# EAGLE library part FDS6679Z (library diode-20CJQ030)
Fairchild's FDS6679Z 30 Volt P-Channel PowerTrench MOSFET General Description: This P-Channel MOSFET has been designed specifically to improve the overall efficiency of DC/DC converters using either synchronous or conventional switching PWM controllers, and battery chargers. These MOSFETs feature faster switching and lower gate charge than other MOSFETs with comparable RDS(ON) specifications. The result is a MOSFET that is easy and safer to drive (even at very high frequencies), and DC/DC power supply designs with higher overall efficiency. Features: -13 A, -30 V. RDS(ON) = 9 mOhm @ VGS = -10 V RDS(ON) = 13 mOhm @ VGS = -4.5 V Extended VGSS range (-25V) for battery applications ESD protection diode (note 3) High performance trench technology for extremely low RDS(ON) High power and current handling capability Please send any comments to: messi@users.sourceforge.net
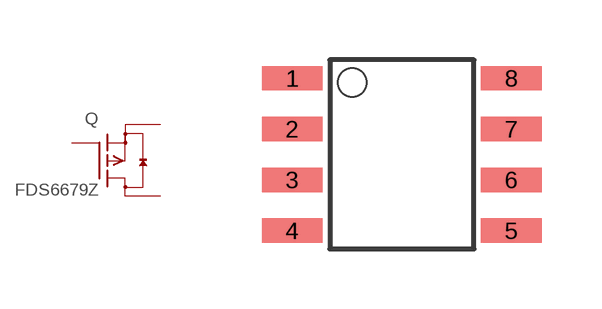
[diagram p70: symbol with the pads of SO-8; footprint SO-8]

Designator prefix Q

## FDS6679Z  [SO-8]
1  S  pas
2  S  pas
3  S  pas
4  G  pas
5  D  pas
6  D  pas
7  D  pas
8  D  pas

## Footprint SO-8 (pad centres in mm)
small outline
smd 1.524 x 0.61: 1 -2.743,1.27; 2 -2.743,0; 3 -2.743,-1.27; 4 -2.743,-2.54; 5 2.743,-2.54; 6 2.743,-1.27; 7 2.743,0; 8 2.743,1.27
